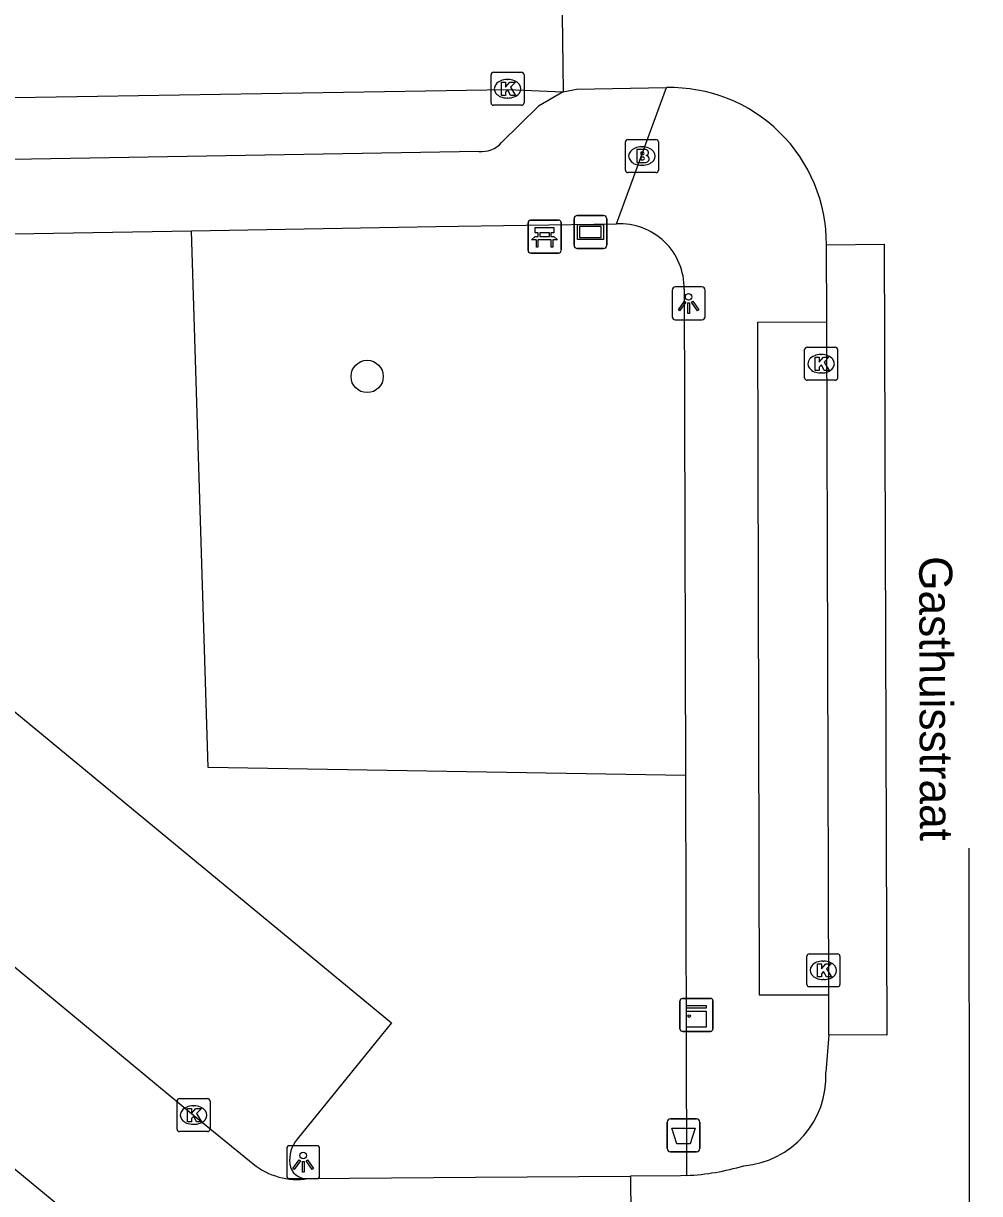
# Model space of a CAD drawing. Extents: x 161882 to 162509, y 381687 to 382379.
# Drawn here: x 162064.58 to 162093.54, y 382216.77 to 382252.2 of the extents above; entities that cross this region are included whole.
import ezdxf

# ---------------------------------------------------------------- set-up
doc = ezdxf.new("R2010")
doc.units = 0
for name, color, linetype in [('IMGEO_Afvalbak', 7, 'Continuous'), ('IMGEO_Bank', 7, 'Continuous'), ('IMGEO_Boom', 7, 'Continuous'), ('IMGEO_Brandkraan', 7, 'Continuous'), ('IMGEO_Groenvoorziening', 7, 'Continuous'), ('IMGEO_Kast', 7, 'Continuous'), ('IMGEO_Kolk', 7, 'Continuous'), ('IMGEO_Lichtpunt', 7, 'Continuous'), ('IMGEO_Openbare_ruimte_label', 7, 'Continuous'), ('IMGEO_Parkeervlak_open', 7, 'Continuous'), ('IMGEO_Rijbaan_lokaal_gesloten', 7, 'Continuous'), ('IMGEO_Rijbaan_lokaal_open', 7, 'Continuous'), ('IMGEO_Verklikker', 7, 'Continuous'), ('IMGEO_Voetpad_open', 7, 'Continuous')]:
    doc.layers.add(name, color=color, linetype=linetype)

msp = doc.modelspace()

# ---------------------------------------------------------------- linework, layer by layer
at = {"layer": 'IMGEO_Afvalbak'}
for p, q in [((162084.079, 382218.134), (162084.079, 382218.934)), ((162084.079, 382218.934), (162084.079, 382218.134)), ((162084.179, 382219.034), (162084.969, 382219.034)), ((162084.969, 382219.034), (162084.179, 382219.034)), ((162085.069, 382218.934), (162085.069, 382218.134)), ((162085.069, 382218.134), (162085.069, 382218.934)), ((162084.969, 382218.034), (162084.179, 382218.034)), ((162084.179, 382218.034), (162084.969, 382218.034))]:
    msp.add_line(p, q, dxfattribs=at)
msp.add_lwpolyline([(162084.222, 382218.748), (162084.926, 382218.748), (162084.777, 382218.278), (162084.371, 382218.278), (162084.222, 382218.748)], dxfattribs=at)
for centre, start, end in [((162084.179, 382218.934), 90, 180), ((162084.179, 382218.934), 90, 180), ((162084.969, 382218.934), 0, 90), ((162084.969, 382218.934), 360, 90), ((162084.179, 382218.134), 180, 270), ((162084.179, 382218.134), 180, 270), ((162084.969, 382218.134), 270, 0), ((162084.969, 382218.134), 270, 0)]:
    msp.add_arc(centre, 0.1, start, end, dxfattribs=at)
at = {"layer": 'IMGEO_Bank'}
for p, q in [((162079.866, 382245.324), (162079.866, 382246.165)), ((162079.866, 382246.165), (162079.866, 382245.324)), ((162079.941, 382246.249), (162080.782, 382246.249)), ((162080.782, 382246.249), (162079.941, 382246.249)), ((162080.866, 382246.174), (162080.866, 382245.333)), ((162080.866, 382245.333), (162080.866, 382246.174)), ((162080.175, 382245.755), (162080.175, 382245.861)), ((162080.219, 382245.861), (162080.219, 382245.755)), ((162080.507, 382245.867), (162080.225, 382245.867)), ((162080.225, 382245.749), (162080.507, 382245.749)), ((162080.513, 382245.755), (162080.513, 382245.861)), ((162080.557, 382245.861), (162080.557, 382245.755)), ((162080.563, 382245.647), (162080.17, 382245.647)), ((162080.791, 382245.249), (162079.95, 382245.249)), ((162079.95, 382245.249), (162080.791, 382245.249))]:
    msp.add_line(p, q, dxfattribs=at)
for points in [[(162080.169, 382245.867), (162080.083, 382245.867), (162080.083, 382246.028), (162080.646, 382246.028), (162080.646, 382245.867), (162080.563, 382245.867)], [(162080.113, 382245.647), (162079.971, 382245.647), (162080.083, 382245.749), (162080.169, 382245.749)], [(162080.563, 382245.749), (162080.646, 382245.749), (162080.758, 382245.647), (162080.619, 382245.647)], [(162080.163, 382245.64), (162080.163, 382245.433), (162080.12, 382245.433), (162080.12, 382245.64)], [(162080.613, 382245.64), (162080.613, 382245.433), (162080.569, 382245.433), (162080.569, 382245.64)]]:
    msp.add_lwpolyline(points, dxfattribs=at)
for centre, radius, start, end in [((162079.944, 382246.171), 0.0779, 92.4484, 184.2845), ((162079.944, 382246.171), 0.0779, 92.4484, 184.2845), ((162080.788, 382246.171), 0.0779, 2.4484, 94.2845), ((162080.788, 382246.171), 0.0779, 2.4484, 94.2845), ((162080.168, 382245.86), 0.00671, 2.8957, 87.1043), ((162080.168, 382245.756), 0.00671, 272.8957, 357.1043), ((162080.225, 382245.86), 0.00671, 92.8957, 177.1043), ((162080.225, 382245.756), 0.00671, 182.8957, 267.1043), ((162080.507, 382245.86), 0.00671, 2.8957, 87.1043), ((162080.507, 382245.756), 0.00671, 272.8957, 357.1043), ((162080.564, 382245.86), 0.00671, 92.8957, 177.1043), ((162080.564, 382245.756), 0.00671, 182.8957, 267.1043), ((162079.944, 382245.327), 0.0779, 182.4484, 274.2845), ((162079.944, 382245.327), 0.0779, 182.4484, 274.2845), ((162080.113, 382245.64), 0.00671, 2.8957, 87.1043), ((162080.17, 382245.64), 0.00671, 92.8957, 177.1043), ((162080.562, 382245.64), 0.00671, 2.8957, 87.1043), ((162080.619, 382245.64), 0.00671, 92.8957, 177.1043), ((162080.788, 382245.327), 0.0779, 272.4484, 4.2845), ((162080.788, 382245.327), 0.0779, 272.4484, 4.2845)]:
    msp.add_arc(centre, radius, start, end, dxfattribs=at)
at = {"layer": 'IMGEO_Boom'}
msp.add_circle((162074.991, 382241.513), 0.489, dxfattribs=at)
at = {"layer": 'IMGEO_Brandkraan'}
for p, q in [((162082.813, 382247.762), (162082.813, 382248.614)), ((162082.888, 382248.688), (162083.74, 382248.688)), ((162083.814, 382248.614), (162083.814, 382247.762)), ((162083.301, 382248.468), (162083.326, 382248.468)), ((162083.324, 382247.908), (162083.299, 382247.908)), ((162083.74, 382247.688), (162082.888, 382247.688))]:
    msp.add_line(p, q, dxfattribs=at)
for points in [[(162082.813, 382247.762), (162082.813, 382248.614)], [(162082.888, 382248.688), (162083.74, 382248.688)], [(162083.814, 382248.614), (162083.814, 382247.762)], [(162083.161, 382248.388), (162083.161, 382247.988), (162083.374, 382247.988)], [(162083.392, 382248.388), (162083.161, 382248.388)], [(162083.34, 382248.307), (162083.286, 382248.307), (162083.286, 382248.231)], [(162083.286, 382248.231), (162083.339, 382248.231)], [(162083.348, 382248.155), (162083.286, 382248.155), (162083.286, 382248.074)], [(162083.286, 382248.074), (162083.348, 382248.074)], [(162083.74, 382247.688), (162082.888, 382247.688)]]:
    msp.add_lwpolyline(points, dxfattribs=at)
for centre, radius, start, end in [((162082.89, 382248.612), 0.0765, 91.552, 178.448), ((162082.89, 382248.612), 0.0765, 91.552, 178.448), ((162083.738, 382248.612), 0.0765, 1.552, 88.448), ((162083.738, 382248.612), 0.0765, 1.552, 88.448), ((162083.341, 382248.269), 0.0379, 267.8285, 90.9355), ((162083.349, 382248.114), 0.0404, 269.8759, 90.5077), ((162083.396, 382248.243), 0.145, 59.4692, 91.5367), ((162083.421, 382248.29), 0.0922, 285.5137, 58.1501), ((162083.426, 382248.098), 0.105, 301.3115, 78.989), ((162083.38, 382248.239), 0.251, 268.6676, 293.5347), ((162082.89, 382247.764), 0.0765, 181.552, 268.448), ((162082.89, 382247.764), 0.0765, 181.552, 268.448), ((162083.738, 382247.764), 0.0765, 271.552, 358.448), ((162083.738, 382247.764), 0.0765, 271.552, 358.448)]:
    msp.add_arc(centre, radius, start, end, dxfattribs=at)
for centre, major_axis, ratio, start_param, end_param in [((162083.3, 382248.188), (-0.387, 0.002), 0.722429, 4.712389, 7.853982), ((162083.325, 382248.188), (-0.39, 0.002), 0.717154, 1.570796, 4.712389)]:
    msp.add_ellipse(centre, major_axis=major_axis, ratio=ratio, start_param=start_param, end_param=end_param, dxfattribs=at)
at = {"layer": 'IMGEO_Groenvoorziening'}
msp.add_lwpolyline([(162084.635, 382229.433), (162070.179, 382229.669), (162069.671, 382245.926)], dxfattribs=at)
at = {"layer": 'IMGEO_Kast'}
for p, q in [((162084.541, 382222.68), (162085.382, 382222.68)), ((162085.382, 382222.68), (162084.541, 382222.68)), ((162084.466, 382221.755), (162084.466, 382222.596)), ((162084.466, 382222.596), (162084.466, 382221.755)), ((162085.466, 382222.605), (162085.466, 382221.764)), ((162085.466, 382221.764), (162085.466, 382222.605)), ((162085.391, 382221.68), (162084.55, 382221.68)), ((162084.55, 382221.68), (162085.391, 382221.68))]:
    msp.add_line(p, q, dxfattribs=at)
for points in [[(162084.661, 382222.47), (162085.261, 382222.47), (162085.261, 382222.385), (162084.661, 382222.385), (162084.661, 382222.47)], [(162084.661, 382222.295), (162085.261, 382222.295), (162085.261, 382221.806), (162084.661, 382221.806), (162084.661, 382222.295)]]:
    msp.add_lwpolyline(points, dxfattribs=at)
msp.add_circle((162084.745, 382222.144), 0.0377, dxfattribs=at)
for centre, start, end in [((162084.544, 382222.602), 92.4484, 184.2845), ((162084.544, 382222.602), 92.4484, 184.2845), ((162085.388, 382222.602), 2.4484, 94.2845), ((162085.388, 382222.602), 2.4484, 94.2845), ((162084.544, 382221.758), 182.4484, 274.2845), ((162084.544, 382221.758), 182.4484, 274.2845), ((162085.388, 382221.758), 272.4484, 4.2845), ((162085.388, 382221.758), 272.4484, 4.2845)]:
    msp.add_arc(centre, 0.0779, start, end, dxfattribs=at)
at = {"layer": 'IMGEO_Kolk'}
for p, q in [((162078.743, 382249.799), (162078.743, 382250.651)), ((162078.818, 382250.725), (162079.67, 382250.725)), ((162079.744, 382250.651), (162079.744, 382249.799)), ((162079.231, 382250.505), (162079.256, 382250.505)), ((162079.254, 382249.945), (162079.229, 382249.945)), ((162079.67, 382249.725), (162078.818, 382249.725)), ((162088.243, 382241.473), (162088.243, 382242.325)), ((162088.318, 382242.399), (162089.17, 382242.399)), ((162088.731, 382242.179), (162088.756, 382242.179)), ((162089.244, 382242.325), (162089.244, 382241.473)), ((162088.754, 382241.619), (162088.729, 382241.619)), ((162089.17, 382241.399), (162088.318, 382241.399)), ((162088.31, 382223.104), (162088.31, 382223.956)), ((162088.385, 382224.03), (162089.237, 382224.03)), ((162088.798, 382223.81), (162088.823, 382223.81)), ((162089.311, 382223.956), (162089.311, 382223.104)), ((162089.237, 382223.03), (162088.385, 382223.03)), ((162088.821, 382223.25), (162088.796, 382223.25)), ((162069.231, 382218.721), (162069.231, 382219.573)), ((162069.306, 382219.647), (162070.158, 382219.647)), ((162070.232, 382219.573), (162070.232, 382218.721)), ((162069.719, 382219.427), (162069.744, 382219.427)), ((162069.742, 382218.867), (162069.717, 382218.867)), ((162070.158, 382218.647), (162069.306, 382218.647))]:
    msp.add_line(p, q, dxfattribs=at)
for points in [[(162078.743, 382249.799), (162078.743, 382250.651)], [(162078.818, 382250.725), (162079.67, 382250.725)], [(162079.744, 382250.651), (162079.744, 382249.799)], [(162079.064, 382250.425), (162079.187, 382250.425), (162079.187, 382250.274), (162079.317, 382250.425), (162079.481, 382250.425), (162079.335, 382250.274), (162079.488, 382250.025), (162079.336, 382250.025), (162079.251, 382250.189), (162079.187, 382250.122), (162079.187, 382250.025), (162079.064, 382250.025), (162079.064, 382250.425)], [(162079.67, 382249.725), (162078.818, 382249.725)], [(162088.243, 382241.473), (162088.243, 382242.325)], [(162088.318, 382242.399), (162089.17, 382242.399)], [(162089.244, 382242.325), (162089.244, 382241.473)], [(162088.564, 382242.099), (162088.687, 382242.099), (162088.687, 382241.948), (162088.817, 382242.099), (162088.981, 382242.099), (162088.835, 382241.948), (162088.988, 382241.699), (162088.836, 382241.699), (162088.751, 382241.863), (162088.687, 382241.796), (162088.687, 382241.699), (162088.564, 382241.699), (162088.564, 382242.099)], [(162089.17, 382241.399), (162088.318, 382241.399)], [(162088.31, 382223.104), (162088.31, 382223.956)], [(162088.385, 382224.03), (162089.237, 382224.03)], [(162088.631, 382223.73), (162088.754, 382223.73), (162088.754, 382223.579), (162088.884, 382223.73), (162089.048, 382223.73), (162088.902, 382223.579), (162089.055, 382223.33), (162088.903, 382223.33), (162088.818, 382223.494), (162088.754, 382223.427), (162088.754, 382223.33), (162088.631, 382223.33), (162088.631, 382223.73)], [(162089.311, 382223.956), (162089.311, 382223.104)], [(162089.237, 382223.03), (162088.385, 382223.03)], [(162069.231, 382218.721), (162069.231, 382219.573)], [(162069.306, 382219.647), (162070.158, 382219.647)], [(162070.232, 382219.573), (162070.232, 382218.721)], [(162069.552, 382219.347), (162069.675, 382219.347), (162069.675, 382219.196), (162069.805, 382219.347), (162069.969, 382219.347), (162069.823, 382219.196), (162069.976, 382218.947), (162069.824, 382218.947), (162069.739, 382219.111), (162069.675, 382219.044), (162069.675, 382218.947), (162069.552, 382218.947), (162069.552, 382219.347)], [(162070.158, 382218.647), (162069.306, 382218.647)]]:
    msp.add_lwpolyline(points, dxfattribs=at)
for centre, start, end in [((162078.82, 382250.649), 91.552, 178.448), ((162078.82, 382250.649), 91.552, 178.448), ((162079.668, 382250.649), 1.552, 88.448), ((162079.668, 382250.649), 1.552, 88.448), ((162078.82, 382249.801), 181.552, 268.448), ((162078.82, 382249.801), 181.552, 268.448), ((162079.668, 382249.801), 271.552, 358.448), ((162079.668, 382249.801), 271.552, 358.448), ((162088.32, 382242.323), 91.552, 178.448), ((162088.32, 382242.323), 91.552, 178.448), ((162089.168, 382242.323), 1.552, 88.448), ((162089.168, 382242.323), 1.552, 88.448), ((162088.32, 382241.475), 181.552, 268.448), ((162088.32, 382241.475), 181.552, 268.448), ((162089.168, 382241.475), 271.552, 358.448), ((162089.168, 382241.475), 271.552, 358.448), ((162088.387, 382223.954), 91.552, 178.448), ((162088.387, 382223.954), 91.552, 178.448), ((162089.235, 382223.954), 1.552, 88.448), ((162089.235, 382223.954), 1.552, 88.448), ((162088.387, 382223.106), 181.552, 268.448), ((162088.387, 382223.106), 181.552, 268.448), ((162089.235, 382223.106), 271.552, 358.448), ((162089.235, 382223.106), 271.552, 358.448), ((162069.308, 382219.571), 91.552, 178.448), ((162069.308, 382219.571), 91.552, 178.448), ((162070.156, 382219.571), 1.552, 88.448), ((162070.156, 382219.571), 1.552, 88.448), ((162069.308, 382218.723), 181.552, 268.448), ((162069.308, 382218.723), 181.552, 268.448), ((162070.156, 382218.723), 271.552, 358.448), ((162070.156, 382218.723), 271.552, 358.448)]:
    msp.add_arc(centre, 0.0765, start, end, dxfattribs=at)
for centre, major_axis, ratio, start_param, end_param in [((162079.23, 382250.225), (-0.387, 0.002), 0.722429, 4.712389, 7.853982), ((162079.255, 382250.225), (-0.39, 0.002), 0.717154, 1.570796, 4.712389), ((162088.73, 382241.899), (-0.387, 0.002), 0.722429, 4.712389, 7.853982), ((162088.755, 382241.899), (-0.39, 0.002), 0.717154, 1.570796, 4.712389), ((162088.797, 382223.53), (-0.387, 0.002), 0.722429, 4.712389, 7.853982), ((162088.822, 382223.53), (-0.39, 0.002), 0.717154, 1.570796, 4.712389), ((162069.718, 382219.147), (-0.387, 0.002), 0.722429, 4.712389, 7.853982), ((162069.743, 382219.147), (-0.39, 0.002), 0.717154, 1.570796, 4.712389)]:
    msp.add_ellipse(centre, major_axis=major_axis, ratio=ratio, start_param=start_param, end_param=end_param, dxfattribs=at)
at = {"layer": 'IMGEO_Lichtpunt'}
for p, q in [((162084.231, 382244.13), (162084.231, 382243.323)), ((162084.231, 382244.13), (162084.231, 382243.323)), ((162085.133, 382244.225), (162084.325, 382244.225)), ((162085.133, 382244.225), (162084.325, 382244.225)), ((162085.227, 382243.323), (162085.227, 382244.13)), ((162085.227, 382243.323), (162085.227, 382244.13)), ((162084.325, 382243.229), (162085.133, 382243.229)), ((162084.325, 382243.229), (162085.133, 382243.229)), ((162072.555, 382218.125), (162072.555, 382217.318)), ((162072.555, 382218.125), (162072.555, 382217.318)), ((162073.457, 382218.22), (162072.649, 382218.22)), ((162073.457, 382218.22), (162072.649, 382218.22)), ((162073.551, 382217.318), (162073.551, 382218.125)), ((162073.551, 382217.318), (162073.551, 382218.125)), ((162072.649, 382217.224), (162073.457, 382217.224)), ((162072.649, 382217.224), (162073.457, 382217.224))]:
    msp.add_line(p, q, dxfattribs=at)
for points in [[(162084.605, 382243.794), (162084.644, 382243.766), (162084.456, 382243.504), (162084.418, 382243.531), (162084.605, 382243.794)], [(162084.707, 382243.746), (162084.754, 382243.746), (162084.754, 382243.424), (162084.707, 382243.424), (162084.707, 382243.746)], [(162084.817, 382243.766), (162084.855, 382243.793), (162085.042, 382243.531), (162085.003, 382243.503), (162084.817, 382243.766)], [(162072.929, 382217.789), (162072.968, 382217.761), (162072.78, 382217.499), (162072.742, 382217.526), (162072.929, 382217.789)], [(162073.031, 382217.741), (162073.078, 382217.741), (162073.078, 382217.419), (162073.031, 382217.419), (162073.031, 382217.741)], [(162073.141, 382217.761), (162073.179, 382217.788), (162073.366, 382217.526), (162073.327, 382217.498), (162073.141, 382217.761)]]:
    msp.add_lwpolyline(points, dxfattribs=at)
for centre in [(162084.73, 382243.928), (162073.054, 382217.923)]:
    msp.add_circle(centre, 0.0994, dxfattribs=at)
for centre, start, end in [((162084.325, 382244.13), 90, 180), ((162084.325, 382244.13), 90, 180), ((162085.133, 382244.13), 0, 90), ((162085.133, 382244.13), 0, 90), ((162084.325, 382243.323), 180, 270), ((162084.325, 382243.323), 180, 270), ((162085.133, 382243.323), 270, 0), ((162085.133, 382243.323), 270, 360), ((162072.649, 382218.125), 90, 180), ((162072.649, 382218.125), 90, 180), ((162073.457, 382218.125), 0, 90), ((162073.457, 382218.125), 0, 90), ((162072.649, 382217.318), 180, 270), ((162072.649, 382217.318), 180, 270), ((162073.457, 382217.318), 270, 0), ((162073.457, 382217.318), 270, 360)]:
    msp.add_arc(centre, 0.0946, start, end, dxfattribs=at)
at = {"layer": 'IMGEO_Parkeervlak_open'}
msp.add_lwpolyline([(162059.248, 382231.094), (162061.467, 382233.7), (162075.73, 382221.944), (162072.866, 382218.419)], dxfattribs=at)
for centre, radius, start, end in [((162073.659, 382217.78), 1.018, 141.1412, 186.4261), ((162073.151, 382217.731), 0.509, 187.3591, 274.2466)]:
    msp.add_arc(centre, radius, start, end, dxfattribs=at)
at = {"layer": 'IMGEO_Rijbaan_lokaal_gesloten'}
for points in [[(162088.905, 382245.498), (162090.649, 382245.517), (162090.73, 382221.57), (162088.975, 382221.581)], [(162088.916, 382243.166), (162088.905, 382245.498)], [(162088.977, 382222.779), (162088.916, 382243.166)], [(162093.544, 382208.615), (162093.544, 382208.615), (162093.251, 382208.601), (162093.226, 382227.208), (162093.226, 382227.227)], [(162088.975, 382221.581), (162088.977, 382222.779)]]:
    msp.add_lwpolyline(points, dxfattribs=at)
at = {"layer": 'IMGEO_Rijbaan_lokaal_open'}
for points in [[(162080.849, 382256.349), (162080.926, 382250.13)], [(162058.178, 382249.872), (162063.043, 382249.938), (162066.82, 382250), (162079.246, 382250.204), (162080.926, 382250.13)], [(162080.926, 382250.13), (162081.33, 382250.21), (162084.055, 382250.261)], [(162059.444, 382227.647), (162059.628, 382227.498), (162069.727, 382219.146), (162071.54, 382217.674)], [(162088.975, 382221.581), (162088.887, 382220.442)], [(162062.715, 382218.833), (162065.737, 382216.341)], [(162084.67, 382217.319), (162084.486, 382217.312), (162082.973, 382217.297)], [(162073.189, 382217.224), (162078.27, 382217.266), (162082.973, 382217.297)], [(162082.973, 382217.297), (162083.011, 382212.494)]]:
    msp.add_lwpolyline(points, dxfattribs=at)
for centre, radius, start, end in [((162084.168, 382245.525), 4.737, 359.6749, 91.3621), ((162086.181, 382220.312), 2.709, 274.6631, 2.7418), ((162072.864, 382219.28), 2.082, 230.4972, 278.975), ((162084.331, 382224.582), 7.271, 272.6731, 286.5413)]:
    msp.add_arc(centre, radius, start, end, dxfattribs=at)
at = {"layer": 'IMGEO_Verklikker'}
for p, q in [((162081.358, 382246.388), (162082.148, 382246.388)), ((162082.148, 382246.388), (162081.358, 382246.388)), ((162081.258, 382245.488), (162081.258, 382246.288)), ((162081.258, 382246.288), (162081.258, 382245.488)), ((162082.248, 382246.288), (162082.248, 382245.488)), ((162082.248, 382245.488), (162082.248, 382246.288)), ((162082.148, 382245.388), (162081.358, 382245.388)), ((162081.358, 382245.388), (162082.148, 382245.388))]:
    msp.add_line(p, q, dxfattribs=at)
for points in [[(162081.359, 382246.12), (162082.147, 382246.12), (162082.147, 382245.656), (162081.359, 382245.656), (162081.359, 382246.12)], [(162081.424, 382246.055), (162081.424, 382245.721), (162082.082, 382245.721), (162082.082, 382246.055), (162081.424, 382246.055)]]:
    msp.add_lwpolyline(points, dxfattribs=at)
for centre, start, end in [((162081.358, 382246.288), 90, 180), ((162081.358, 382246.288), 90, 180), ((162082.148, 382246.288), 0, 90), ((162082.148, 382246.288), 360, 90), ((162081.358, 382245.488), 180, 270), ((162081.358, 382245.488), 180, 270), ((162082.148, 382245.488), 270, 0), ((162082.148, 382245.488), 270, 0)]:
    msp.add_arc(centre, 0.1, start, end, dxfattribs=at)
at = {"layer": 'IMGEO_Voetpad_open'}
for points in [[(162080.926, 382250.13), (162080.177, 382249.699), (162079.065, 382248.596)], [(162082.549, 382246.131), (162084.055, 382250.261)], [(162078.373, 382248.328), (162061.28, 382248.035)], [(162069.671, 382245.926), (162077.067, 382246.054), (162082.549, 382246.131)], [(162061.3, 382245.783), (162069.671, 382245.926)], [(162084.593, 382244.161), (162084.635, 382229.433)], [(162088.977, 382222.779), (162086.88, 382222.774), (162086.821, 382243.155), (162088.916, 382243.166)], [(162084.635, 382229.433), (162084.67, 382217.319)]]:
    msp.add_lwpolyline(points, dxfattribs=at)
for centre, radius, start, end in [((162078.456, 382249.142), 0.818, 264.2068, 318.1343), ((162082.655, 382244.195), 1.939, 358.9923, 93.12)]:
    msp.add_arc(centre, radius, start, end, dxfattribs=at)

# ---------------------------------------------------------------- texts
at = {"layer": 'IMGEO_Openbare_ruimte_label'}
msp.add_text('Gasthuisstraat', height=1, rotation=270.1719, dxfattribs=at).set_placement((162091.714, 382236.07))

doc.saveas('drawing.dxf')
